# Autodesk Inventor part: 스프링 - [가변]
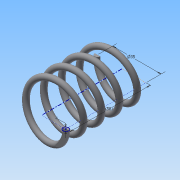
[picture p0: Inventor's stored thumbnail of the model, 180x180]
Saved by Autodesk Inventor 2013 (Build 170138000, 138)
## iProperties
Created: 2015-03
Part Number: 스프링 - [가변]
Material: 강철, 탄소
Document SubType Name: Modeling
Designer: Administrator
Density: 7.87 g/cm^3
Mass: 47.9946 g
Surface Area: 62.0026 cm^2
Volume: 6.09842 cm^3
Author: Administrator
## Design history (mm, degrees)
sketch "스케치1"
  geometry: L1 (0, 0)-(17.5, 0); L2 (17.5, 0)-(17.5, 43.5); L3 (17.5, 43.5)-(0, 43.5); L4 (0, 43.5)-(0, 0); C1 r 2 at (17.5, 0)
  constraints: 8 end point, 2 parallel, 1 centre point, 1 coincident, 1 horizontal, 1 perpendicular
  dimensions: "d0" = 43.5 distance of L1.end L2.end (derived); "d2" = 35 diameter of L2 L4; "d3" = 4 diameter of C1
feature "코일1" sketch "스케치1" pitch "d4" = 10; turns "d6" = 4.5; dims "d5" = 43.5 (= d0), "d7" = 0, angle "d8" = 90 deg, angle "d9" = 90 deg, "d10" = 0, "d11" = 0
node "작업 평면1"
sketch "스케치2"
  geometry: L1 (15.5, 0)-(19.5, 0) reference; 1 further point
  constraints: 1 horizontal alignment
extrude "돌출1" cut sketch "스케치2" stored distance "d13" = 10; taper "d14" = 0 deg
node "작업 평면2"
sketch "스케치3"
  geometry: L1 (15.5, 0)-(19.5, 0) reference; 1 further point
  constraints: 1 horizontal alignment
extrude "돌출2" cut sketch "스케치3" stored distance "d16" = 10; taper "d17" = 0 deg
node "솔리드1"
node "절단 모서리 투영1"
node "절단 모서리 투영2"
other parameters: "d12" = 0, "d15" = -43.5 (= -d0)
